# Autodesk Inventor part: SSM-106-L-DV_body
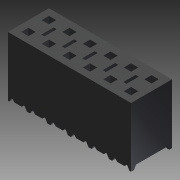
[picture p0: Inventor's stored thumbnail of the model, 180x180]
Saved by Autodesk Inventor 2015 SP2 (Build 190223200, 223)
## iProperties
Category: PARTsolutions
Company: SAMTEC
Created: 2015-08
Part Number: SSM-106-L-DV_body
Catalog Web Link: www.cadenas.de
Description: SSM Series Body-SSM Series - (2,54 mm) .100" Tiger Claw™ Surface Mount Socket
Vendor: SAMTEC
Document SubType Name: Modeling
Designer: PARTuser1
Manufacturer: SAMTEC
Mass: 0.466796 g
Surface Area: 7.69049 cm^2
Volume: 0.466796 cm^3
Density: 1 g/cm^3
Material: Allgemein
Appearance: PSOLRGB-127-127-127
PSOL_IDENT_0: {$CADENAS_DATA\23d-libs\samtec\modelling\ssm\parts\ssm_body.prj},243 {VTYP=3D},{NB=SSM-106-L-DV_body
PSOL_IDENT_1: },{LINA=SSM-106-L-DV_body},{NN=SSM Series Body},{DATE=25.05.2015 10:50:41},{GEOMDATE=25.05.2015 10:4
PSOL_IDENT_2: 9:00},{VERSION=},{LINEID=10},{LINESUBID=-1},{WBVAR=POS,ROW,PLOPT,BEOPT,LCOPT,POLOPT,AOPT,POPT,MOPT,K
PSOL_IDENT_3: OPT,TROPT}  {NB=SSM-106-L-DV_body},{LINA=SSM-106-L-DV_body},{KT=DUMMY},{PN=SSM-106-L-DV},{SERIES=SSM
PSOL_IDENT_4: },{POS=6},{POSPN=06},{ROW=-DV},{ROWALG= '-SV','-SV - Single Vertical','-SH','-SH - Single Horizontal'
PSOL_IDENT_5: ,'-DH','-DH - Double Horizontal','-DV','-DV - Double Vertical' },{PLOPT=-L},{PLOPTALG= '-S','-S - 30
PSOL_IDENT_6: micro\" Selective Gold in Contact Area, Matte Tin on Tail','-L','-L - 10micro\" Light Selective Gold
PSOL_IDENT_7: in Contact Area, Matte Tin on Tail','-T','-T - Matte Tin Contact and Tail','-F','-F - 3micro\" Flas
PSOL_IDENT_8: h Selective Gold Contact, Matte Tin on Tail','-H','-H - 30micro\" Heavy Gold in Contact Area, 3micro
PSOL_IDENT_9: \" on Tail','-STL','-STL - 30micro\" Selective Gold in Contact Area, Tin/Lead (90/10+/-5%) Tail','-S
PSOL_IDENT_10: M','-SM - 30micro\" Selective Gold in Contact Area, Matte Tin on Tail','-LM','-LM - 10micro\" Light
PSOL_IDENT_11: Selective Gold in Contact Area, Matte Tin Tail','-TM','-TM - Matte Tin Contact and tail','-FM','-FM
PSOL_IDENT_12: - 3micro\" Flash Selective Gold in Contact Area, Matte Tin Tail' },{BEOPT=},{BEOPTALG= '','Not Selec
PSOL_IDENT_13: ted','-BE','-BE - Bottom Entry' },{LCOPT=},{LCOPTALG= '','Not Selected','-LC','-LC Locking Clip' },{
PSOL_IDENT_14: POLOPT=},{POLOPTALG= '','Not Selected','001','001','002','002','003','003','004','004','005','005','
PSOL_IDENT_15: 006','006','007','007','008','008','009','009','010','010','011','011','012','012' },{POLOPTMAX=144}
PSOL_IDENT_16: ,{POLOPTMAX2='001','001','002','002','003','003','004','004','005','005','006','006','007','007','00
PSOL_IDENT_17: 8','008','009','009','010','010','011','011','012','012'},{POLARIZE='001','001','002','002','003','0
PSOL_IDENT_18: 03','004','004','005','005','006','006','007','007','008','008','009','009','010','010','011','011','
PSOL_IDENT_19: 012','012','013','013','014','014','015','015','016','016','017','017','018','018','019','019','020'
PSOL_IDENT_20: ,'020','021','021','022','022','023','023','024','024','025','025','026','026','027','027','028','02
PSOL_IDENT_21: 8','029','029','030','030','031','031','032','032','033','033','034','034','035','035','036','036','
PSOL_IDENT_22: 037','037','038','038','039','039','040','040','041','041','042','042','043','043','044','044','045'
PSOL_IDENT_23: ,'045','046','046','047','047','048','048','049','049','050','050','051','051','052','052','053','05
PSOL_IDENT_24: 3','054','054','055','055','056','056','057','057','058','058','059','059','060','060','061','061','
PSOL_IDENT_25: 062','062','063','063','064','064','065','065','066','066','067','067','068','068','069','069','070'
PSOL_IDENT_26: ,'070','071','071','072','072','073','073','074','074','075','075','076','076','077','077','078','07
PSOL_IDENT_27: 8','079','079','080','080'},{POLOPTATOF=0},{POLOPTPN=},{AOPT=},{AOPTALG= '','Not Selected','-A','-A
PSOL_IDENT_28: - Alignment Pin' },{POPT=},{POPTALG= '','Not Selected','-P','-P - Pick & Place Pad' },{MOPT=},{MOPTA
PSOL_IDENT_29: LG= '','Not Selected','-M','-M - Metal Pick & Place Pad' },{KOPT=},{KOPTALG= '','Not Selected','-K','
PSOL_IDENT_30: -K - Polyimide Film Pad' },{TROPT=},{TROPALG= '','Not Selected','-TR','-TR - Tape & Reel'  },{OE=2},
PSOL_IDENT_31: {S=0.10250},{SK=0.17200},{SM=0.18050},{POLOE=2}
NN: SSM Series Body
NT: SSM Series - (2,54 mm) .100" Tiger Claw™ Surface Mount Socket
NB: SSM-106-L-DV_body
NBSYN: $PN._body
LINA: SSM-106-L-DV_body
SERIES: SSM
POS: 6
ROW: -DV - Double Vertical
PLOPT: -L - 10micro" Light Selective Gold in Contact Area, Matte Tin on Tail
BEOPT: Not Selected
LCOPT: Not Selected
POLOPT: Not Selected
AOPT: Not Selected
POPT: Not Selected
MOPT: Not Selected
KOPT: Not Selected
TROPT: Not Selected
SUPPLIER: SAMTEC
ARTICLENO: SSM-106-L-DV_body
BOMINFO: SSM-106-L-DV_body
CREATOR: CADENAS GmbH
Title: SSM-106-L-DV_body
Author: Cadenas PARTsolutions
Comments: SSM Series - (2,54 mm) .100" Tiger Claw™ Surface Mount Socket
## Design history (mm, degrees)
sketch "Sketch_1"
  geometry: L1 (7.62, -2.54)-(7.62, 2.54); L2 (7.62, 2.54)-(-7.62, 2.54); L3 (-7.62, 2.54)-(-7.62, -2.54); L4 (-7.62, -2.54)-(7.62, -2.54); L5 (-5.905, 0.826)-(-5.905, 1.714); L6 (-5.905, 1.714)-(-6.795, 1.714); L7 (-6.795, 1.714)-(-6.795, 0.826); L8 (-6.795, 0.826)-(-5.905, 0.826); L9 (-5.905, -1.714)-(-5.905, -0.826); L10 (-5.905, -0.826)-(-6.795, -0.826); L11 (-6.795, -0.826)-(-6.795, -1.714); L12 (-6.795, -1.714)-(-5.905, -1.714); L13 (-3.365, 0.826)-(-3.365, 1.714); L14 (-3.365, 1.714)-(-4.255, 1.714); L15 (-4.255, 1.714)-(-4.255, 0.826); L16 (-4.255, 0.826)-(-3.365, 0.826); L17 (-3.365, -1.714)-(-3.365, -0.826); L18 (-3.365, -0.826)-(-4.255, -0.826); L19 (-4.255, -0.826)-(-4.255, -1.714); L20 (-4.255, -1.714)-(-3.365, -1.714); L21 (-0.826, 0.826)-(-0.826, 1.714); L22 (-0.826, 1.714)-(-1.714, 1.714); L23 (-1.714, 1.714)-(-1.714, 0.826); L24 (-1.714, 0.826)-(-0.826, 0.826); L25 (-0.826, -1.714)-(-0.826, -0.826); L26 (-0.826, -0.826)-(-1.714, -0.826); L27 (-1.714, -0.826)-(-1.714, -1.714); L28 (-1.714, -1.714)-(-0.826, -1.714); L29 (1.714, 0.826)-(1.714, 1.714); L30 (1.714, 1.714)-(0.826, 1.714); L31 (0.826, 1.714)-(0.826, 0.826); L32 (0.826, 0.826)-(1.714, 0.826); L33 (1.714, -1.714)-(1.714, -0.826); L34 (1.714, -0.826)-(0.826, -0.826); L35 (0.826, -0.826)-(0.826, -1.714); L36 (0.826, -1.714)-(1.714, -1.714); L37 (4.255, 0.826)-(4.255, 1.714); L38 (4.255, 1.714)-(3.365, 1.714); L39 (3.365, 1.714)-(3.365, 0.826); L40 (3.365, 0.826)-(4.255, 0.826); L41 (4.255, -1.714)-(4.255, -0.826); L42 (4.255, -0.826)-(3.365, -0.826); L43 (3.365, -0.826)-(3.365, -1.714); L44 (3.365, -1.714)-(4.255, -1.714); L45 (6.795, 0.826)-(6.795, 1.714); L46 (6.795, 1.714)-(5.905, 1.714); L47 (5.905, 1.714)-(5.905, 0.826); L48 (5.905, 0.826)-(6.795, 0.826); L49 (6.795, -1.714)-(6.795, -0.826); L50 (6.795, -0.826)-(5.905, -0.826); L51 (5.905, -0.826)-(5.905, -1.714); L52 (5.905, -1.714)-(6.795, -1.714)
  constraints: 104 end point
extrude "Extrusion1" join sketch "Sketch_1" distance "d0" = 7.366; taper "d1" = 0 deg
sketch "Sketch_3"
  geometry: L1 (0, 2.184)-(-0.254, 2.184); L2 (-0.254, 2.184)-(-0.254, -2.184); L3 (-0.254, -2.184)-(0, -2.184); L4 (0, -2.184)-(0.457, -1.92); L5 (0.457, -1.92)-(0.457, 1.92); L6 (0.457, 1.92)-(0, 2.184)
  constraints: 12 end point
extrude "Extrusion2" cut sketch "Sketch_3" stored distance "d2" = 30.48; taper "d3" = 0 deg
sketch "Sketch_2"
  geometry: L1 (-7.585, -2.54)-(93.945, -2.54); L2 (93.945, -2.54)-(93.945, -0.254); L3 (93.945, -0.254)-(93.51, 0.457); L4 (93.51, 0.457)-(93.383, 0.457); L5 (93.383, 0.457)-(93.154, 0.203); L6 (93.154, 0.203)-(92.266, 0.203); L7 (92.266, 0.203)-(92.037, 0.457); L8 (92.037, 0.457)-(91.91, 0.457); L9 (91.91, 0.457)-(91.475, -0.254); L10 (91.475, -0.254)-(91.405, -0.254); L11 (91.405, -0.254)-(90.97, 0.457); L12 (90.97, 0.457)-(90.843, 0.457); L13 (90.843, 0.457)-(90.615, 0.203); L14 (90.615, 0.203)-(89.725, 0.203); L15 (89.725, 0.203)-(89.497, 0.457); L16 (89.497, 0.457)-(89.37, 0.457); L17 (89.37, 0.457)-(88.935, -0.254); L18 (88.935, -0.254)-(88.865, -0.254); L19 (88.865, -0.254)-(88.43, 0.457); L20 (88.43, 0.457)-(88.303, 0.457); L21 (88.303, 0.457)-(88.075, 0.203); L22 (88.075, 0.203)-(87.186, 0.203); L23 (87.186, 0.203)-(86.957, 0.457); L24 (86.957, 0.457)-(86.83, 0.457); L25 (86.83, 0.457)-(86.395, -0.254); L26 (86.395, -0.254)-(86.325, -0.254); L27 (86.325, -0.254)-(85.89, 0.457); L28 (85.89, 0.457)-(85.763, 0.457); L29 (85.763, 0.457)-(85.534, 0.203); L30 (85.534, 0.203)-(84.646, 0.203); L31 (84.646, 0.203)-(84.417, 0.457); L32 (84.417, 0.457)-(84.29, 0.457); L33 (84.29, 0.457)-(83.855, -0.254); L34 (83.855, -0.254)-(83.785, -0.254); L35 (83.785, -0.254)-(83.35, 0.457); L36 (83.35, 0.457)-(83.223, 0.457); L37 (83.223, 0.457)-(82.995, 0.203); L38 (82.995, 0.203)-(82.106, 0.203); L39 (82.106, 0.203)-(81.877, 0.457); L40 (81.877, 0.457)-(81.75, 0.457); L41 (81.75, 0.457)-(81.315, -0.254); L42 (81.315, -0.254)-(81.245, -0.254); L43 (81.245, -0.254)-(80.81, 0.457); L44 (80.81, 0.457)-(80.683, 0.457); L45 (80.683, 0.457)-(80.455, 0.203); L46 (80.455, 0.203)-(79.566, 0.203); L47 (79.566, 0.203)-(79.337, 0.457); L48 (79.337, 0.457)-(79.21, 0.457); L49 (79.21, 0.457)-(78.775, -0.254); L50 (78.775, -0.254)-(78.705, -0.254); L51 (78.705, -0.254)-(78.27, 0.457); L52 (78.27, 0.457)-(78.143, 0.457); L53 (78.143, 0.457)-(77.915, 0.203); L54 (77.915, 0.203)-(77.025, 0.203); L55 (77.025, 0.203)-(76.797, 0.457); L56 (76.797, 0.457)-(76.67, 0.457); L57 (76.67, 0.457)-(76.235, -0.254); L58 (76.235, -0.254)-(76.165, -0.254); L59 (76.165, -0.254)-(75.73, 0.457); L60 (75.73, 0.457)-(75.603, 0.457); L61 (75.603, 0.457)-(75.374, 0.203); L62 (75.374, 0.203)-(74.486, 0.203); L63 (74.486, 0.203)-(74.257, 0.457); L64 (74.257, 0.457)-(74.13, 0.457)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
  constraints: 644 end point
extrude "Extrusion3" cut sketch "Sketch_2" stored distance "d4" = 5.08; taper "d5" = 0 deg
sketch "Sketch_24"
  geometry: L1 (-5.271, 7.747)-(-5.271, 5.207); L2 (-5.271, 5.207)-(-4.889, 5.207); L3 (-4.889, 5.207)-(-4.889, 7.366); L4 (-4.889, 7.366)-(-2.731, 7.366); L5 (-2.731, 7.366)-(-2.731, 5.207); L6 (-2.731, 5.207)-(-2.349, 5.207); L7 (-2.349, 5.207)-(-2.349, 7.366); L8 (-2.349, 7.366)-(-0.191, 7.366); L9 (-0.191, 7.366)-(-0.191, 5.207); L10 (-0.191, 5.207)-(0.191, 5.207); L11 (0.191, 5.207)-(0.191, 7.366); L12 (0.191, 7.366)-(2.349, 7.366); L13 (2.349, 7.366)-(2.349, 5.207); L14 (2.349, 5.207)-(2.731, 5.207); L15 (2.731, 5.207)-(2.731, 7.366); L16 (2.731, 7.366)-(4.889, 7.366); L17 (4.889, 7.366)-(4.889, 5.207); L18 (4.889, 5.207)-(5.271, 5.207); L19 (5.271, 5.207)-(5.271, 7.747); L20 (5.271, 7.747)-(-5.271, 7.747)
  constraints: 40 end point
extrude "Extrusion4" cut sketch "Sketch_24" stored distance "d6" = 1.524; taper "d7" = 0 deg
node "body_XY"
node "body_YZ"
node "body_ZX"
node "body_X"
node "body_Y"
node "body_Z"
node "body_Center"
node "terminal_XY"
node "terminal_YZ"
node "terminal_ZX"
node "terminal_X"
node "terminal_Y"
node "terminal_Z"
node "terminal_Center"
body "Solid1"
